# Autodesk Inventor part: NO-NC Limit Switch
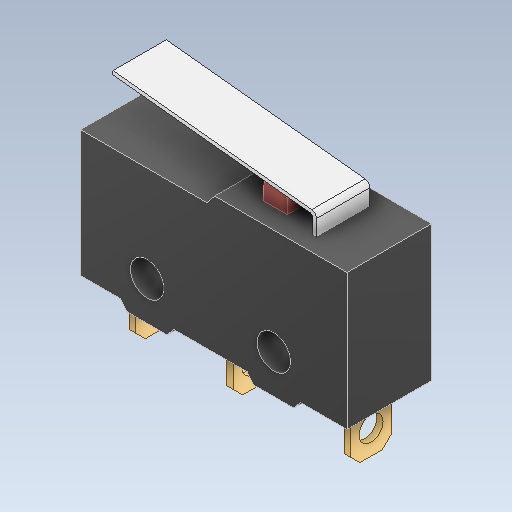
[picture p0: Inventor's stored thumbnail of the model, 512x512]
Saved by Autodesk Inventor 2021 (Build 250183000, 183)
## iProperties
Created: 2026-01
Part Number: NO-NC Limit Switch
Material: Acciaio
Document SubType Name: Modeling
Designer: hp
Density: 7.85 g/cm^3
Appearance: Default
Author: hp
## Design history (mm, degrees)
feature "Solido1"
feature "Solido2"
feature "Solido3"
feature "Solido4"
feature "Solido5"
feature "Solido6"
body "Solid1"
body "Solid2"
body "Solid3"
body "Solid4"
body "Solid5"
body "Solid6"
